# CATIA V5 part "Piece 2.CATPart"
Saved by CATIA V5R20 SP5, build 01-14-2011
Part number: Piece 2
Bounding box of the stored display mesh (mm): x -50 to 300, y 500 to 870, z -50 to 50
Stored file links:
  G:\IAO Final\Piece 2.CATPart
  G:\IAO Final\Assemblage Final.CATProduct
  G:\IAO Final\SKL Piece 2.CATPart
  G:\IAO Final\SKL Roue.CATPart
  G:\IAO Final\Tige.CATPart
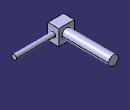
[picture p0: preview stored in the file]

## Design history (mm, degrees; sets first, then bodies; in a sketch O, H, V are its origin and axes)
External parameters (linked from other documents)
  `External.Rayon excentrique` = 15 mm
Set1
  Plane1: linked copy from another document
  Point1: linked copy from another document
  Line1: linked copy from another document
Body1 (main body)
  Sketch1 on Plane1, origin (0, 500, 0), H (-1, 0, 0), V (0, 0, 1)
    line L1 (-50, 50) -> (50, 50)
    line L2 (50, 50) -> (50, -50)
    line L3 (50, -50) -> (-50, -50)
    line L4 (-50, -50) -> (-50, 50)
    length L1 = 100
    length L2 = 100
    distance H L3 = 50
    distance V L2 = 50
    horizontal: L1 H, L3 H
    vertical: L2 V, L4 V
  Pad1: profile Sketch1, direction (0, 1, 0), length 70
  Sketch2 on end face of Pad1, origin (0, 570, 0), H (-1, 0, 0), V (0, 0, 1)
    circle A1 centre (0, 0) radius 30
    point P1 (0, 0)
    reference projected point E1 (0, 0) from Point1
    radius A1 = 30
    coincidence: E1 P1
  Pad2: profile Sketch2, direction (0, 1, 0), length 300
  Sketch3 on face of Pad1 from Sketch1.L4, origin (50, 0, 0), H (0, 1, 0), V (0, 0, 1)
    circle A1 centre (535, 0) radius 15
    point P1 (535, 0)
    reference projected line E1 through (0, 0) direction (1, 0) from Line1
    reference projected line E2 (570, 50) -> (570, -50) from edge [face of Pad1 from Sketch1.L4 | end face of Pad1]
    distance P1 E2 = 35
    radius A1 = 15 {= `External.Rayon excentrique`}
    coincidence: P1 E1
  Pad3: profile Sketch3, direction (1, 0, 0), length 250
